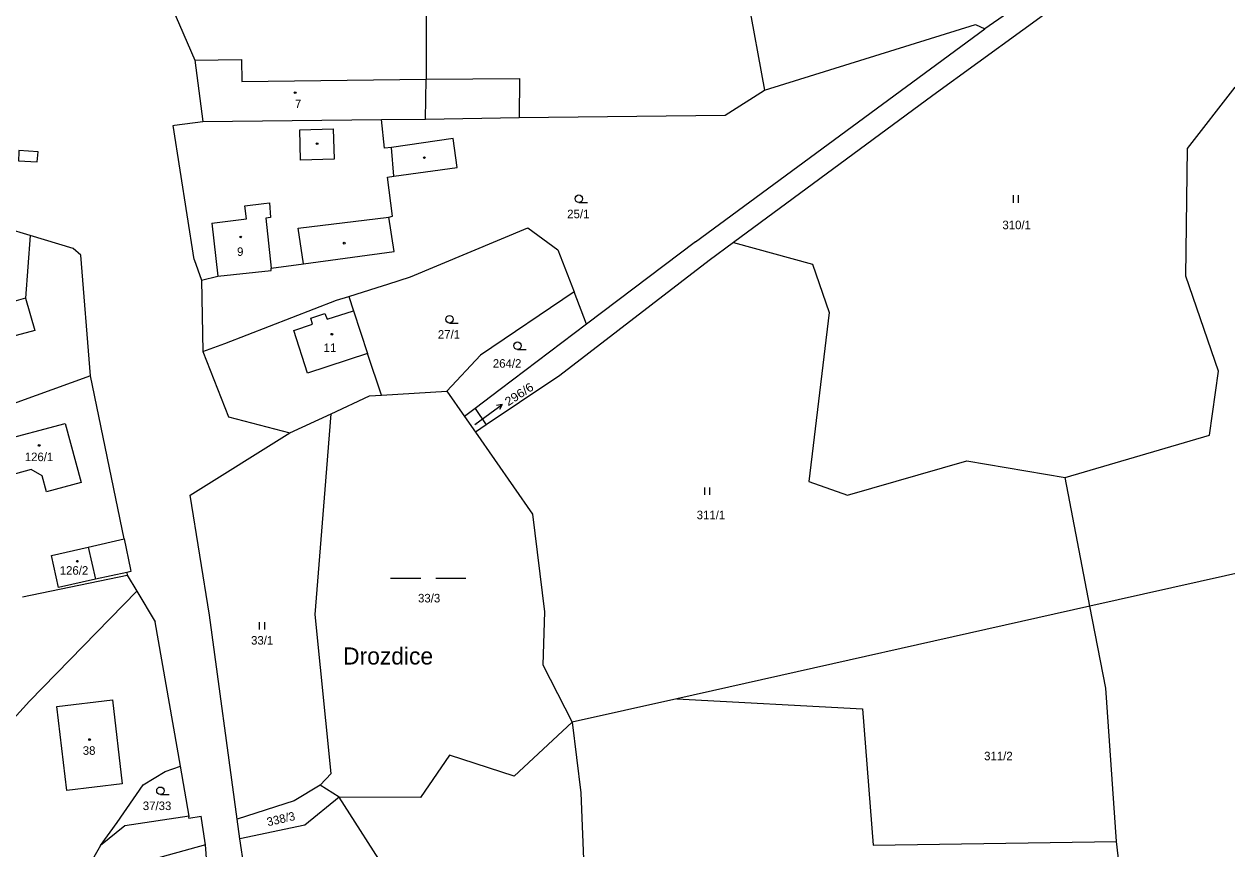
# Model space of a CAD drawing. Extents: x -645290 to -643454, y -1064771 to -1062356.
# Drawn here: x -644577 to -644337.3, y -1063831.9 to -1063667.6 of the extents above; entities that cross this region are included whole.
import ezdxf
from ezdxf.enums import TextEntityAlignment as Align

# ---------------------------------------------------------------- set-up
doc = ezdxf.new("R2010")
doc.units = 0
doc.header["$LTSCALE"] = 0.68
for name, color, linetype, lineweight in [('1', 7, 'Continuous', 25), ('13', 7, 'Continuous', 13), ('3', 7, 'Continuous', 25), ('4', 7, 'Continuous', 13), ('5', 7, 'Continuous', 25), ('7', 7, 'Continuous', 13)]:
    doc.layers.add(name, color=color, linetype=linetype, lineweight=lineweight)
doc.layers.add('2', color=7, linetype='Continuous')

msp = doc.modelspace()

# ---------------------------------------------------------------- linework, layer by layer
at = {"layer": '1'}
for p, q in [((-644437.84, -1063635.07), (-644429.45, -1063680.78)), ((-644342.53, -1063638.64), (-644385.58, -1063668.54)), ((-644365.33, -1063659.58), (-644395.9, -1063681.86)), ((-644496.92, -1063662.78), (-644496.93, -1063678.61)), ((-644547.55, -1063664.21), (-644542.97, -1063674.78)), ((-644429.45, -1063680.78), (-644387.42, -1063667.71)), ((-644387.42, -1063667.71), (-644385.58, -1063668.54)), ((-644443.2, -1063710.99), (-644385.58, -1063668.54)), ((-644542.97, -1063674.78), (-644541.42, -1063686.99)), ((-644496.93, -1063678.61), (-644478.31, -1063678.43)), ((-644478.31, -1063678.43), (-644478.39, -1063686.22)), ((-644437.3, -1063685.72), (-644429.45, -1063680.78)), ((-644395.9, -1063681.86), (-644435.62, -1063711.13)), ((-644345.2, -1063692.39), (-644335.66, -1063680.17)), ((-644547.02, -1063687.73), (-644541.42, -1063686.99)), ((-644541.42, -1063686.99), (-644505.77, -1063686.63)), ((-644505.77, -1063686.63), (-644497.01, -1063686.53)), ((-644505.19, -1063692.35), (-644505.77, -1063686.63)), ((-644497.01, -1063686.53), (-644478.39, -1063686.22)), ((-644478.39, -1063686.22), (-644437.3, -1063685.72)), ((-644547.34, -1063687.79), (-644547.02, -1063687.73)), ((-644543.12, -1063714.52), (-644547.34, -1063687.79)), ((-644491.54, -1063690.38), (-644503.83, -1063692.16)), ((-644490.74, -1063696.16), (-644491.54, -1063690.38)), ((-644503.83, -1063692.16), (-644505.19, -1063692.35)), ((-644345.51, -1063717.83), (-644345.2, -1063692.39)), ((-644503.33, -1063697.89), (-644490.74, -1063696.16)), ((-644504.61, -1063698.07), (-644503.33, -1063697.89)), ((-644503.6, -1063705.88), (-644504.61, -1063698.07)), ((-644504.32, -1063706.07), (-644503.6, -1063705.88)), ((-644503.27, -1063712.89), (-644504.32, -1063706.07)), ((-644575.8, -1063709.73), (-644580.67, -1063708.27)), ((-644500.01, -1063717.98), (-644476.62, -1063708.18)), ((-644476.62, -1063708.18), (-644470.66, -1063712.56)), ((-644575.8, -1063709.73), (-644576.72, -1063722.21)), ((-644567.22, -1063712.31), (-644575.8, -1063709.73)), ((-644443.2, -1063710.99), (-644464.95, -1063727.41)), ((-644565.69, -1063713.66), (-644567.22, -1063712.31)), ((-644521.37, -1063715.34), (-644503.27, -1063712.89)), ((-644470.66, -1063712.56), (-644467.43, -1063720.96)), ((-644435.62, -1063711.13), (-644440.47, -1063714.7)), ((-644435.62, -1063711.13), (-644419.89, -1063715.41)), ((-644563.78, -1063737.68), (-644565.69, -1063713.66)), ((-644543.12, -1063714.52), (-644541.64, -1063718.6)), ((-644527.82, -1063716.22), (-644521.37, -1063715.34)), ((-644440.47, -1063714.7), (-644470.28, -1063737.61)), ((-644419.89, -1063715.41), (-644416.56, -1063725.07)), ((-644541.64, -1063718.6), (-644538.4, -1063717.84)), ((-644538.4, -1063717.84), (-644527.78, -1063716.67)), ((-644527.78, -1063716.67), (-644527.82, -1063716.22)), ((-644504.54, -1063719.4), (-644500.01, -1063717.98)), ((-644338.98, -1063736.73), (-644345.51, -1063717.83)), ((-644541.64, -1063718.6), (-644541.39, -1063732.82)), ((-644512.32, -1063721.85), (-644506.69, -1063720.09)), ((-644506.69, -1063720.09), (-644504.54, -1063719.4)), ((-644576.72, -1063722.21), (-644574.87, -1063728.66)), ((-644537.04, -1063731.26), (-644514.76, -1063722.62)), ((-644514.76, -1063722.62), (-644512.32, -1063721.85)), ((-644512.32, -1063721.85), (-644511.38, -1063724.7)), ((-644467.43, -1063720.96), (-644486.09, -1063733.56)), ((-644464.95, -1063727.41), (-644467.43, -1063720.96)), ((-644511.38, -1063724.7), (-644508.57, -1063733.19)), ((-644416.56, -1063725.07), (-644420.65, -1063758.75)), ((-644464.95, -1063727.41), (-644482.14, -1063740.38)), ((-644574.87, -1063728.66), (-644597.97, -1063734.84)), ((-644541.39, -1063732.82), (-644537.04, -1063731.26)), ((-644541.39, -1063732.82), (-644536.32, -1063745.87)), ((-644505.81, -1063741.53), (-644508.57, -1063733.19)), ((-644486.09, -1063733.56), (-644492.79, -1063740.73)), ((-644340.79, -1063749.51), (-644338.98, -1063736.73)), ((-644563.78, -1063737.68), (-644612.27, -1063755.14)), ((-644557.1, -1063770.14), (-644563.78, -1063737.68)), ((-644470.28, -1063737.61), (-644478.28, -1063742.97)), ((-644515.86, -1063745.23), (-644508.19, -1063741.68)), ((-644508.19, -1063741.68), (-644505.81, -1063741.53)), ((-644505.81, -1063741.53), (-644492.79, -1063740.73)), ((-644492.79, -1063740.73), (-644489.26, -1063745.75)), ((-644482.14, -1063740.38), (-644487.14, -1063744.15)), ((-644487.14, -1063744.15), (-644489.26, -1063745.75)), ((-644487.14, -1063744.15), (-644484.96, -1063747.44)), ((-644478.28, -1063742.97), (-644484.96, -1063747.44)), ((-644536.32, -1063745.87), (-644524.04, -1063749.02)), ((-644524.04, -1063749.02), (-644515.86, -1063745.23)), ((-644517.05, -1063760.31), (-644515.86, -1063745.23)), ((-644489.26, -1063745.75), (-644487.09, -1063748.87)), ((-644582.49, -1063750.8), (-644568.82, -1063747.14)), ((-644568.82, -1063747.14), (-644565.68, -1063758.89)), ((-644543.94, -1063761.43), (-644524.04, -1063749.02)), ((-644484.96, -1063747.44), (-644487.09, -1063748.87)), ((-644487.09, -1063748.87), (-644475.68, -1063765.21)), ((-644369.58, -1063757.9), (-644340.79, -1063749.51)), ((-644575.59, -1063756.34), (-644580.65, -1063757.69)), ((-644573.43, -1063757.57), (-644575.59, -1063756.34)), ((-644412.92, -1063761.45), (-644389.13, -1063754.63)), ((-644389.13, -1063754.63), (-644369.58, -1063757.9)), ((-644572.57, -1063760.75), (-644573.43, -1063757.57)), ((-644565.68, -1063758.89), (-644572.57, -1063760.75)), ((-644420.65, -1063758.75), (-644412.92, -1063761.45)), ((-644364.63, -1063783.55), (-644369.58, -1063757.9)), ((-644519, -1063785.19), (-644517.05, -1063760.31)), ((-644540.05, -1063785.36), (-644543.94, -1063761.43)), ((-644475.68, -1063765.21), (-644473.31, -1063784.7)), ((-644564.24, -1063771.8), (-644557.1, -1063770.14)), ((-644557.1, -1063770.14), (-644555.85, -1063776.23)), ((-644313.05, -1063772), (-644364.63, -1063783.55)), ((-644577.34, -1063781.7), (-644556.45, -1063777.39)), ((-644556.56, -1063776.82), (-644562.79, -1063778.19)), ((-644556.56, -1063776.82), (-644556.45, -1063777.39)), ((-644556.45, -1063777.39), (-644554.54, -1063780.56)), ((-644554.54, -1063780.56), (-644575.96, -1063802.49)), ((-644554.54, -1063780.56), (-644550.88, -1063786.65)), ((-644534.54, -1063825.98), (-644540.05, -1063785.36)), ((-644515.81, -1063816.85), (-644519, -1063785.19)), ((-644473.31, -1063784.7), (-644473.67, -1063795.24)), ((-644364.63, -1063783.55), (-644446.97, -1063801.99)), ((-644361.47, -1063799.9), (-644364.63, -1063783.55)), ((-644545.88, -1063815.44), (-644550.88, -1063786.65)), ((-644473.67, -1063795.24), (-644467.79, -1063806.65)), ((-644446.97, -1063801.99), (-644467.79, -1063806.65)), ((-644446.97, -1063801.99), (-644409.96, -1063804.02)), ((-644359.35, -1063830.45), (-644361.47, -1063799.9)), ((-644575.96, -1063802.49), (-644603.81, -1063833.16)), ((-644570.53, -1063803.55), (-644559.4, -1063802.21)), ((-644568.49, -1063820.26), (-644570.53, -1063803.55)), ((-644559.4, -1063802.21), (-644557.45, -1063818.92)), ((-644409.96, -1063804.02), (-644407.84, -1063831.16)), ((-644467.79, -1063806.65), (-644479.39, -1063817.42)), ((-644467.79, -1063806.65), (-644466.06, -1063820.7)), ((-644492.27, -1063813.23), (-644498.02, -1063821.68)), ((-644479.39, -1063817.42), (-644492.27, -1063813.23)), ((-644553.29, -1063819.17), (-644548.88, -1063816.48)), ((-644548.88, -1063816.48), (-644545.88, -1063815.44)), ((-644544.15, -1063825.38), (-644545.88, -1063815.44)), ((-644557.45, -1063818.92), (-644568.49, -1063820.26)), ((-644518, -1063819.21), (-644515.81, -1063816.85)), ((-644558.47, -1063826.64), (-644553.29, -1063819.17)), ((-644518, -1063819.21), (-644523.2, -1063822.33)), ((-644514.22, -1063821.58), (-644518, -1063819.21)), ((-644466.06, -1063820.7), (-644465.03, -1063846.16)), ((-644523.2, -1063822.33), (-644534.54, -1063825.98)), ((-644514.22, -1063821.58), (-644521.11, -1063827.19)), ((-644492.88, -1063855.02), (-644514.22, -1063821.58)), ((-644498.02, -1063821.68), (-644514.22, -1063821.58)), ((-644544.15, -1063825.38), (-644556.93, -1063827.28)), ((-644544.19, -1063825.8), (-644541.76, -1063825.35)), ((-644544.19, -1063825.8), (-644544.15, -1063825.38)), ((-644541.45, -1063827.16), (-644541.76, -1063825.35)), ((-644534.01, -1063829.87), (-644534.54, -1063825.98)), ((-644561.79, -1063831.23), (-644558.47, -1063826.64)), ((-644556.93, -1063827.28), (-644561.79, -1063831.23)), ((-644540.88, -1063831.09), (-644541.45, -1063827.16)), ((-644521.11, -1063827.19), (-644534.01, -1063829.87)), ((-644533.14, -1063835.63), (-644534.01, -1063829.87)), ((-644407.84, -1063831.16), (-644359.35, -1063830.45)), ((-644343.83, -1063959.61), (-644359.35, -1063830.45)), ((-644561.79, -1063831.23), (-644569.98, -1063845.53)), ((-644540.88, -1063831.09), (-644552.65, -1063834.34)), ((-644538.96, -1063855.68), (-644540.88, -1063831.09))]:
    msp.add_line(p, q, dxfattribs=at)
for points in [[(-644562.79, -1063778.19), (-644570.15, -1063779.82), (-644571.58, -1063773.45), (-644564.24, -1063771.8)], [(-644555.85, -1063776.23), (-644555.76, -1063776.64), (-644556.56, -1063776.82)]]:
    msp.add_lwpolyline(points, dxfattribs=at)
at = {"layer": '13'}
msp.add_lwpolyline([(-644578.1, -1063693.15), (-644578.12, -1063694.85), (-644574.42, -1063695.06), (-644574.22, -1063693.07), (-644578.1, -1063692.82)], close=True, dxfattribs=at)
at = {"layer": '3'}
for p, q in [((-644466.473, -1063703.15), (-644464.723, -1063703.15)), ((-644379.861, -1063703.21), (-644379.861, -1063701.71)), ((-644378.86, -1063703.21), (-644378.86, -1063701.71)), ((-644492.253, -1063727.15), (-644490.503, -1063727.15)), ((-644478.703, -1063732.42), (-644476.953, -1063732.42)), ((-644441.381, -1063761.39), (-644441.381, -1063759.89)), ((-644440.38, -1063761.39), (-644440.38, -1063759.89)), ((-644503.979, -1063777.98), (-644497.979, -1063777.98)), ((-644494.979, -1063777.98), (-644488.979, -1063777.98)), ((-644530.081, -1063788.22), (-644530.081, -1063786.72)), ((-644529.08, -1063788.22), (-644529.08, -1063786.72)), ((-644549.853, -1063821.07), (-644548.103, -1063821.07))]:
    msp.add_line(p, q, dxfattribs=at)
for centre in [(-644466.4729, -1063702.3998), (-644492.2529, -1063726.3998), (-644478.7029, -1063731.6698), (-644549.8529, -1063820.3198)]:
    msp.add_circle(centre, 0.75, dxfattribs=at)
at = {"layer": '4'}
for p, q in [((-644542.97, -1063674.78), (-644533.71, -1063674.67)), ((-644533.71, -1063674.67), (-644533.61, -1063679.05)), ((-644533.61, -1063679.05), (-644496.93, -1063678.61)), ((-644497.01, -1063686.53), (-644496.93, -1063678.61)), ((-644522.06, -1063688.68), (-644515.44, -1063688.45)), ((-644521.97, -1063694.72), (-644522.06, -1063688.68)), ((-644515.44, -1063688.45), (-644515.25, -1063694.5)), ((-644503.33, -1063697.89), (-644503.83, -1063692.16)), ((-644515.25, -1063694.5), (-644521.97, -1063694.72)), ((-644533.06, -1063703.78), (-644529.22, -1063703.33)), ((-644532.71, -1063706.43), (-644533.06, -1063703.78)), ((-644529.22, -1063703.33), (-644528.14, -1063703.19)), ((-644528.14, -1063703.19), (-644527.92, -1063706.15)), ((-644527.92, -1063706.15), (-644528.86, -1063706.25)), ((-644528.86, -1063706.25), (-644527.82, -1063716.22)), ((-644522.42, -1063708.28), (-644504.32, -1063706.07)), ((-644539.62, -1063707.24), (-644532.71, -1063706.43)), ((-644539.62, -1063707.24), (-644538.4, -1063717.84)), ((-644521.37, -1063715.34), (-644522.42, -1063708.28)), ((-644576.72, -1063722.21), (-644584.73, -1063724.44)), ((-644519.86, -1063726.19), (-644517.1, -1063725.27)), ((-644517.1, -1063725.27), (-644516.63, -1063726.41)), ((-644516.63, -1063726.41), (-644511.38, -1063724.7)), ((-644523.3, -1063728.67), (-644519.52, -1063727.4)), ((-644519.52, -1063727.4), (-644519.86, -1063726.19)), ((-644520.53, -1063737.14), (-644523.3, -1063728.67)), ((-644508.57, -1063733.19), (-644520.53, -1063737.14)), ((-644564.24, -1063771.8), (-644562.79, -1063778.19))]:
    msp.add_line(p, q, dxfattribs=at)
at = {"layer": '5'}
for centre in [(-644523.0068, -1063681.2692), (-644518.6368, -1063691.4292), (-644497.2568, -1063694.2092), (-644533.8568, -1063710.0092), (-644513.2168, -1063711.2392), (-644515.6868, -1063729.3892), (-644574.0168, -1063751.5292), (-644566.4068, -1063774.5992), (-644563.9668, -1063810.1292)]:
    msp.add_circle(centre, 0.175, dxfattribs=at)
at = {"layer": '7'}
msp.add_line((-644481.762, -1063743.396), (-644482.867, -1063743.58), dxfattribs=at)
msp.add_lwpolyline([(-644487.21, -1063747.35), (-644484.19, -1063745.16), (-644481.762, -1063743.396), (-644482.278, -1063744.39)], dxfattribs=at)

# ---------------------------------------------------------------- texts
at = {"layer": '2'}
for s, p in [('7', (-644522.41, -1063684.354)), ('25/1', (-644466.579, -1063706.275)), ('9', (-644533.95, -1063713.785)), ('27/1', (-644492.359, -1063730.275)), ('11', (-644516.069, -1063732.925)), ('264/2', (-644480.77, -1063736.054)), ('126/1', (-644574.05, -1063754.665)), ('126/2', (-644567.08, -1063777.285)), ('33/3', (-644496.309, -1063782.804)), ('33/1', (-644529.579, -1063791.205)), ('38', (-644564.069, -1063813.155))]:
    msp.add_text(s, height=1.7, dxfattribs=at).set_placement(p, align=Align.CENTER)
for s, height, p in [('310/1', 1.7, (-644382.07, -1063708.465)), ('296/6', 0.2, (-644487.21, -1063747.4)), ('311/1', 1.7, (-644442.99, -1063766.225)), ('311/2', 1.7, (-644385.71, -1063814.245)), ('37/33', 1.7, (-644553.37, -1063824.165))]:
    msp.add_text(s, height=height, dxfattribs=at).set_placement(p)
at = {"layer": '2', "width": 1.1}
msp.add_text('296/6', height=1.7, rotation=33, dxfattribs=at).set_placement((-644480.538, -1063743.746))
at = {"layer": '2'}
msp.add_text('338/3', height=1.7, rotation=13, dxfattribs=at).set_placement((-644525.6562, -1063826.7615), align=Align.CENTER)
at = {"layer": '7'}
msp.add_text('Drozdice', height=3.4, dxfattribs=at).set_placement((-644513.45, -1063795.17))

doc.saveas('drawing.dxf')
